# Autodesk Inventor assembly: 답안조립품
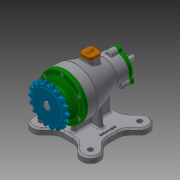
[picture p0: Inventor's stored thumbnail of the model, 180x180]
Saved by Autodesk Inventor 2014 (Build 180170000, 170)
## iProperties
Created: 2018-03
Part Number: 답안조립품
Document SubType Name: Assembly
Designer: 601-10
Author: 601-10
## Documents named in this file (15)
- C:\Users\601-10\Desktop\480308V1001\답안조립품.iam
- C:\Users\601-10\Desktop\480308V1001\본체.ipt
- C:\Users\601-10\Desktop\480308V1001\뒤커버.ipt
- C:\Users\601-10\Desktop\480308V1001\마개.ipt
- C:\Users\601-10\Desktop\480308V1001\베어링-6200.ipt
- C:\Users\601-10\Desktop\480308V1001\베어링-6203.ipt
- C:\Users\601-10\Desktop\480308V1001\볼트 M4 x 12.ipt
- 볼트 M4 x 12.ipt
- C:\Users\601-10\Desktop\480308V1001\스프로킷.ipt
- C:\Users\601-10\Desktop\480308V1001\앞커버.ipt
- C:\Users\601-10\Desktop\480308V1001\오일 실 10 20 7.ipt
- C:\Users\601-10\Desktop\480308V1001\오일 실 17 30 8.ipt
- C:\Users\601-10\Desktop\480308V1001\축.ipt
- C:\Users\601-10\Desktop\480308V1001\키 5 x 5.ipt
- 키 5 x 5.ipt
